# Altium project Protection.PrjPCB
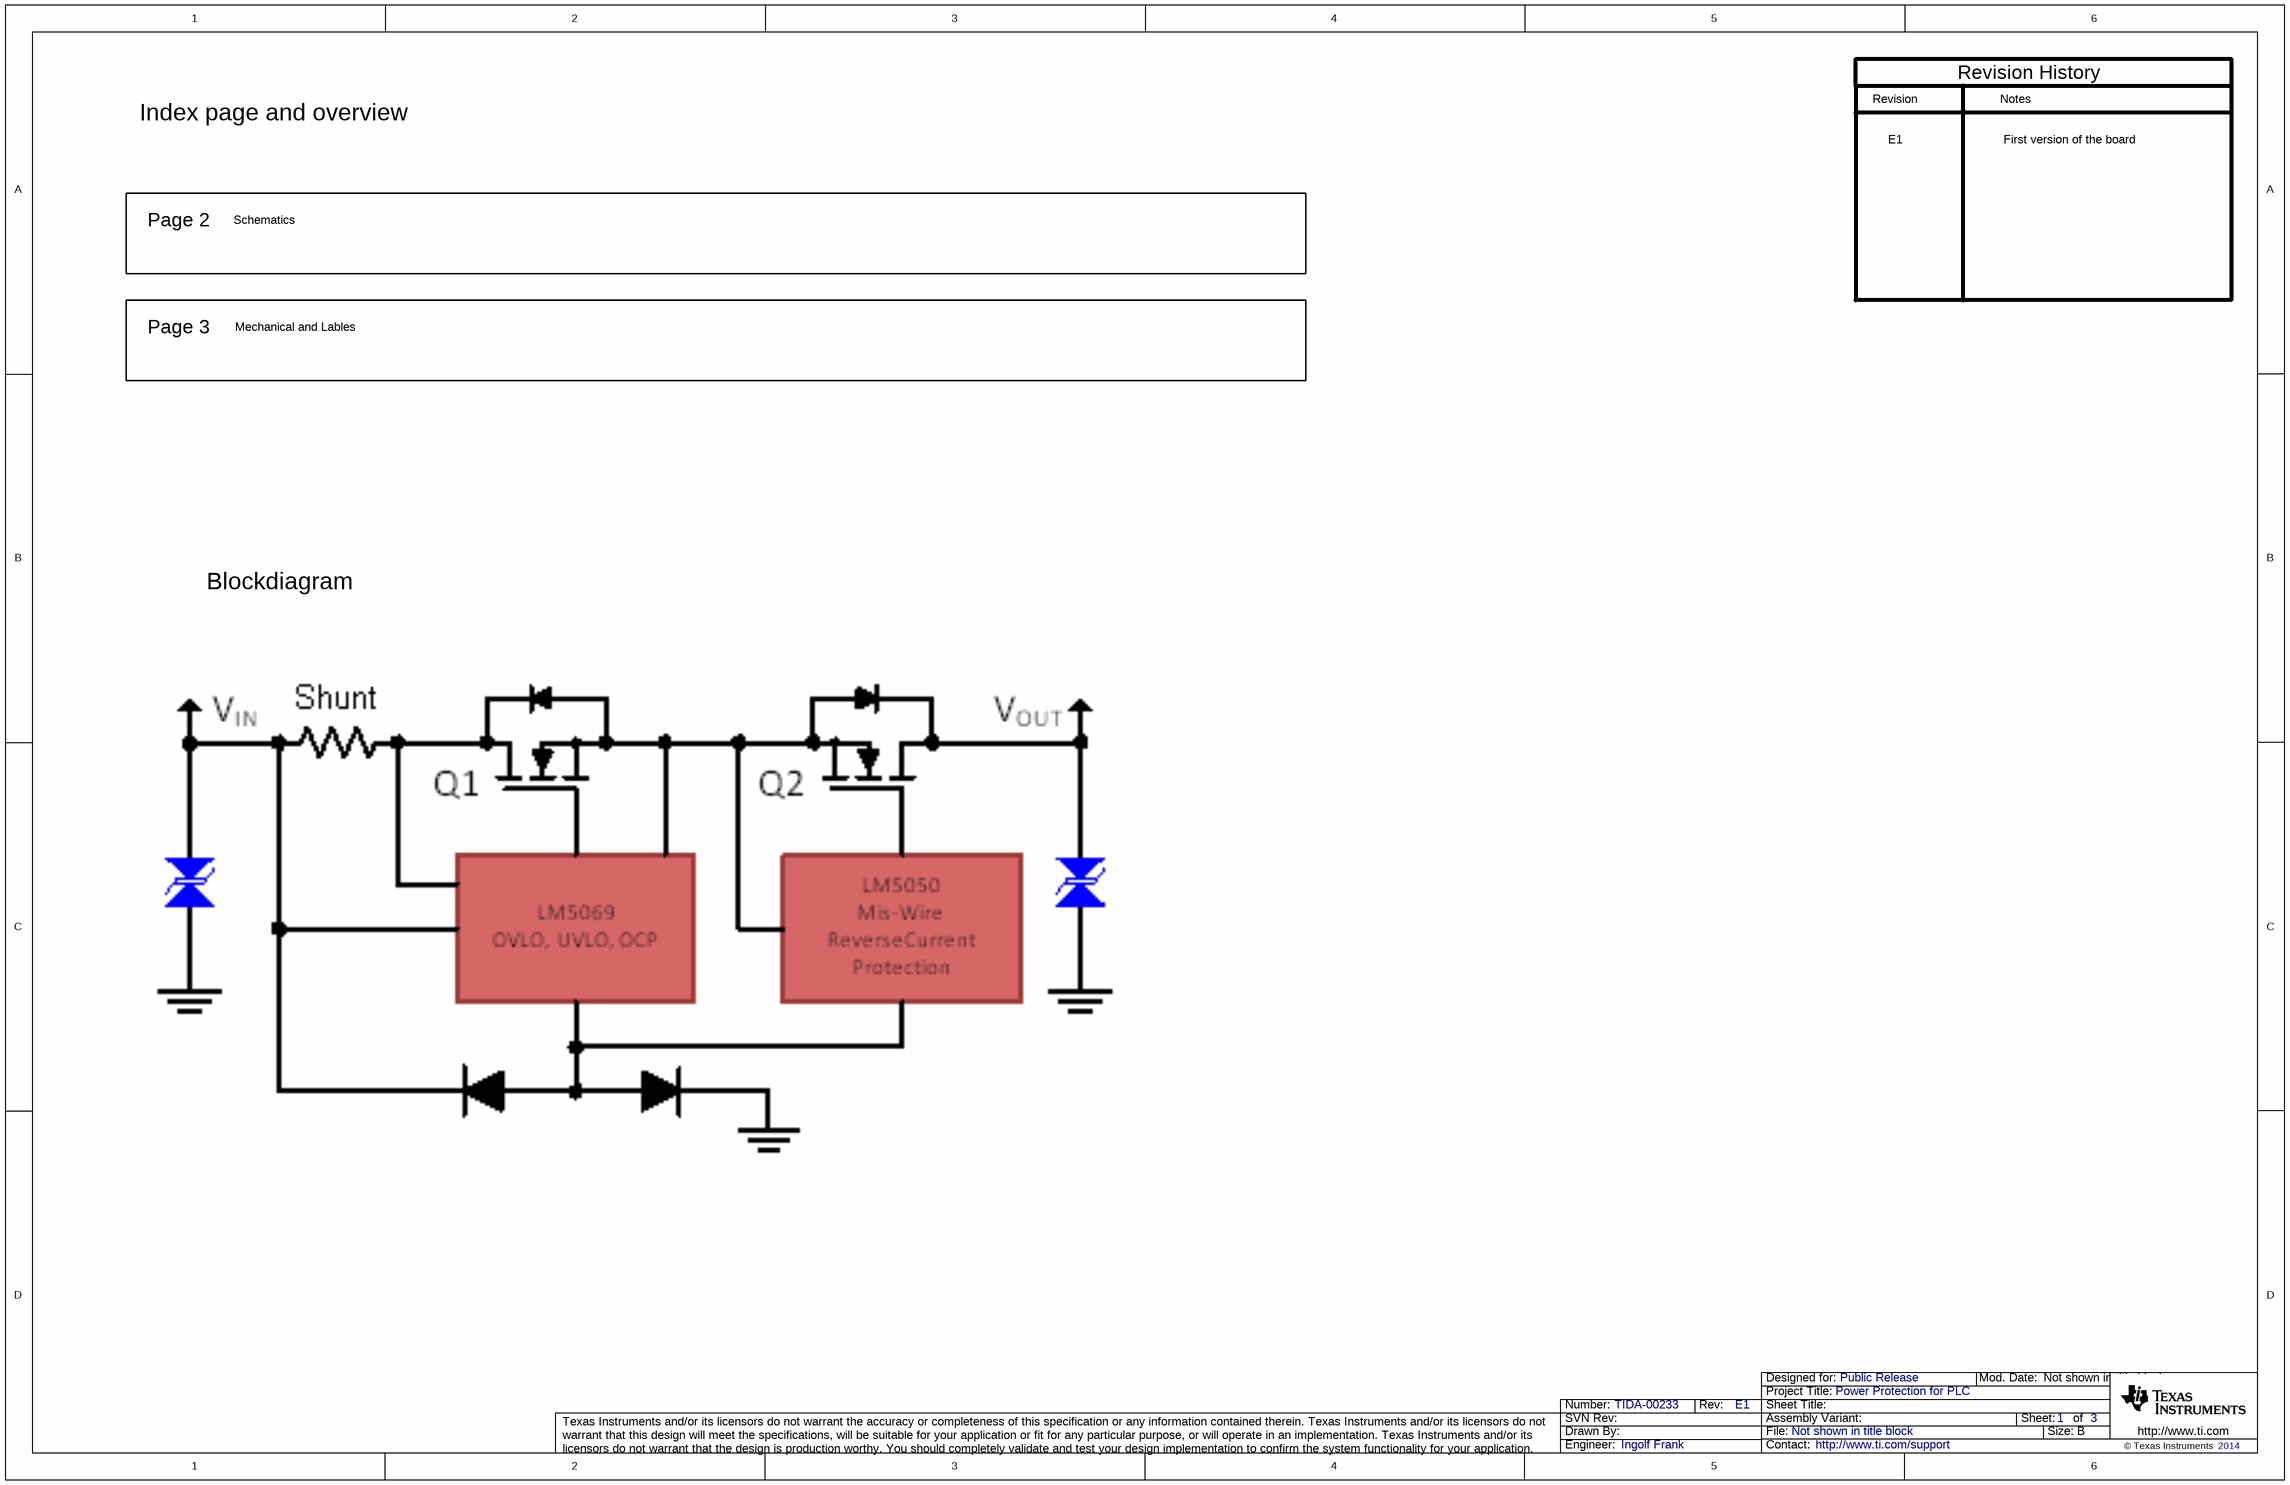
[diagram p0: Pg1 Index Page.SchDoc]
CopyrightYear: 2014; PCB_Layout: Ingolf Frank; PCB_Rev: E1; PRJ_Customer: Public Release; PRJ_Engineer: Ingolf Frank; PRJ_Number: TIDA-00233; PRJ_Title: Power Protection for PLC; SCH_Rev: E1; TechSupport: http://www.ti.com/support
3 sheets, 55 parts. Net scope: global (net labels, ports and power ports of the same name join across sheets).
Board file: Protection_var2.PcbDoc
Sheets:
  Pg1 Index Page.SchDoc
  Pg2 Protection.SchDoc
  Pg3 Hardware.SchDoc

## Sheet Pg1 Index Page.SchDoc
size 431 x 279 mm; Date: Not shown in title block; ApprovedBy: Not shown in title block; CheckedBy: Not shown in title block; Author: Not shown in title block; CompanyName: Not shown in title block; Engineer: Not shown in title block; Organization: Not shown in title block; Address1: Not shown in title block; Address2: Not shown in title block; Address3: Not shown in title block; Address4: Not shown in title block; DocumentNumber: 1; Revision: Use project parameter SCH_Rev; SheetNumber: 1; SheetTotal: 3; PageSetup: Record=PageOptions|CenterHorizontal=True|CenterVertical=True|PrintScale=1.00|XCorrection=1.00|YCorrection=1.00|PrintKind=0|BorderSize=5000000|LeftOffset=0|BottomOffset=0|Orientation=2|PaperLength=1000|PaperWidth=1000|Scale=100|PaperSource=15|PrintQuality=600|MediaType=1|DitherType=10|PaperKind=Letter|PrintScaleMode=1

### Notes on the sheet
- Revision
- Notes
- Revision History
- Index page and overview
- E1
- First version of the board
- Page 2
- Schematics
- Page 3
- Mechanical and Lables
- Blockdiagram

## Sheet Pg2 Protection.SchDoc
size 431 x 279 mm; Date: Not shown in title block; ApprovedBy: Not shown in title block; CheckedBy: Not shown in title block; Author: Not shown in title block; CompanyName: Not shown in title block; Engineer: Not shown in title block; Organization: Not shown in title block; Address1: Not shown in title block; Address2: Not shown in title block; Address3: Not shown in title block; Address4: Not shown in title block; DocumentNumber: 1; Revision: Use project parameter SCH_Rev; SheetNumber: 2; SheetTotal: 3; PageSetup: Record=PageOptions|CenterHorizontal=True|CenterVertical=True|PrintScale=0.64|XCorrection=1.00|YCorrection=1.00|PrintKind=0|BorderSize=5000000|LeftOffset=0|BottomOffset=0|Orientation=2|PaperLength=1000|PaperWidth=1000|Scale=100|PaperSource=15|PrintQuality=600|MediaType=1|DitherType=10|PaperKind=Letter|PrintScaleMode=1
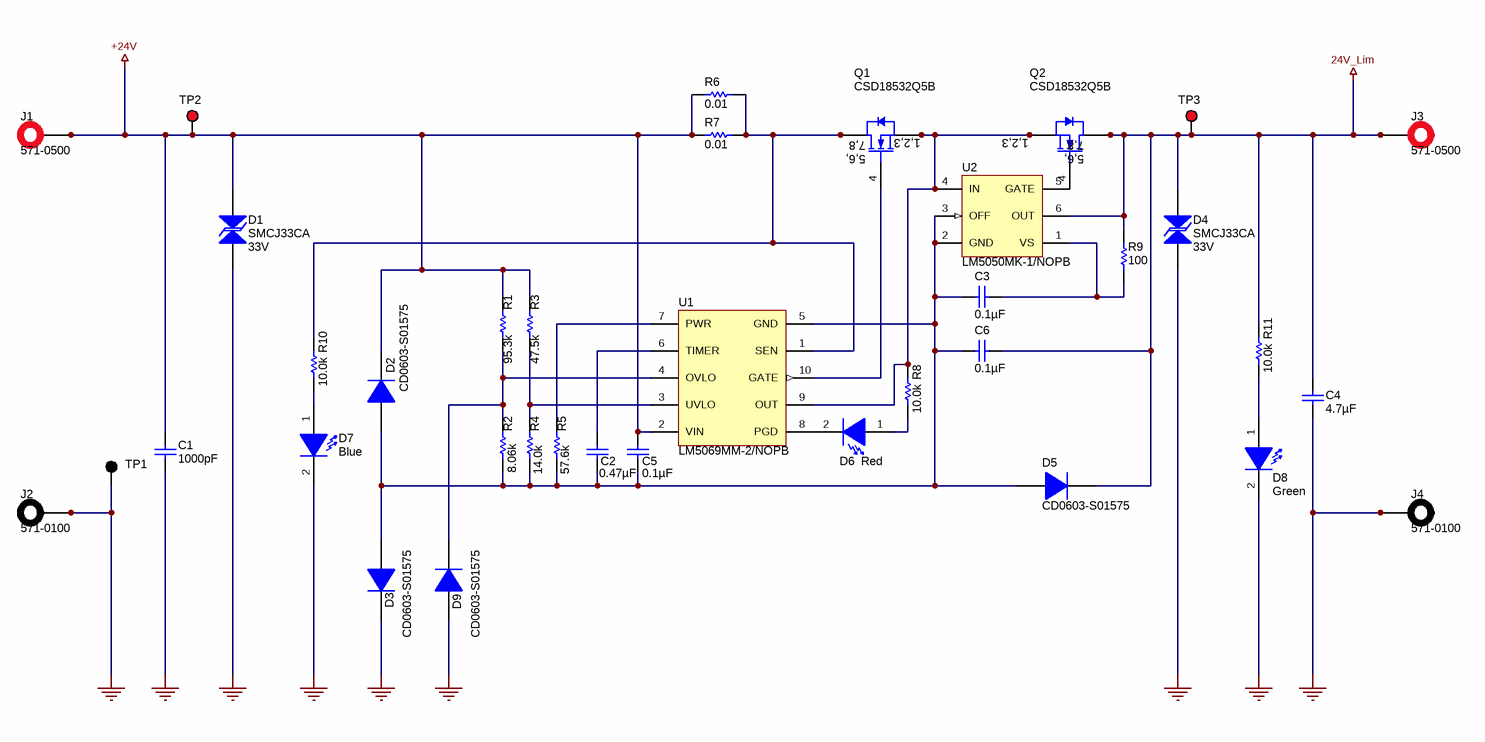
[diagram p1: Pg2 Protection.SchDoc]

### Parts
C1  ValueDisplayed: 1000pF  [0603]  (hidden comment: 06031C102JAT2A)
C2  ValueDisplayed: 0.47µF  [0603]  (hidden comment: UMK107ABJ474KA-T)
C3  ValueDisplayed: 0.1µF  [0603]  (hidden comment: GRM188R72A104KA35D)
C4  ValueDisplayed: 4.7µF  [1210M]  (hidden comment: C3225X7S2A475K200AB)
C5  ValueDisplayed: 0.1µF  [0603]  (hidden comment: GRM188R72A104KA35D)
C6  ValueDisplayed: 0.1µF  [0603]  (hidden comment: GRM188R72A104KA35D)
D1  SMCJ33CA  value 33V  [SMC]
D2  CD0603-S01575  [Diode_0603]
D3  CD0603-S01575  [Diode_0603]
D4  SMCJ33CA  value 33V  [SMC]
D5  CD0603-S01575  [Diode_0603]
D6  value Red  [LED_LTST-C190_Red]  (hidden comment: LTST-C190CKT)
D7  value Blue  [LB Q39G_BLUE]  (hidden comment: LB Q39G-L2N2-35-1)
D8  value Green  [LED_LTST-C190_G]  (hidden comment: LTST-C190KGKT)
D9  CD0603-S01575  [Diode_0603]
J1  571-0500  [571-0500]
J2  571-0100  [571-0100]
J3  571-0500  [571-0500]
J4  571-0100  [571-0100]
Q1  CSD18532Q5B  [TRANS_NexFET_Q5B]
Q2  CSD18532Q5B  [TRANS_NexFET_Q5B]
R1  value 95.3k  [0603_HV]  (hidden comment: CRCW060395K3FKEA)
R2  value 8.06k  [0603_HV]  (hidden comment: CRCW06038K06FKEA)
R3  value 47.5k  [0603_HV]  (hidden comment: CRCW060347K5FKEA)
R4  value 14.0k  [0603_HV]  (hidden comment: CRCW060314K0FKEA)
R5  value 57.6k  [0603_HV]  (hidden comment: CRCW060357K6FKEA)
R6  value 0.01  [1206]  (hidden comment: WSLP1206R0100FEA)
R7  value 0.01  [1206]  (hidden comment: WSLP1206R0100FEA)
R8  value 10.0k  [0603]  (hidden comment: CRCW060310K0FKEA)
R9  value 100  [0603]  (hidden comment: CRCW0603100RFKEA)
R10  value 10.0k  [0603]  (hidden comment: CRCW060310K0FKEA)
R11  value 10.0k  [0603]  (hidden comment: CRCW060310K0FKEA)
TP1  5001  [Keystone5001]  (value not drawn)
TP2  5000  [Keystone5000]  (value not drawn)
TP3  5000  [Keystone5000]  (value not drawn)
U1  LM5069MM-2/NOPB  [MUB10A_N]
U2  LM5050MK-1/NOPB  [DDC0006A_N]

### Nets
24V_Lim: C4.1 C6.1 D4.1 D5.1(K) J3.1 J3.2 Q2.5(D) Q2.6(D) Q2.7(D) Q2.8(D) R9.2 R11.1 TP3.1 U2.6(OUT)
+24V: C1.1 C5.1 D1.1 D2.1(K) J1.1 J1.2 R1.2 R3.2 R6.1 R7.1 TP2.1 U1.2(VIN)
GND: C1.2 C4.2 D1.2 D3.1(K) D4.2 D7.2(K) D8.2(K) D9.2(A) J2.1 J2.2 J4.1 J4.2 TP1.1
NetC2_1: C2.1 U1.6(TIMER)
NetC2_2: C2.2 C3.2 C5.2 C6.2 D2.2(A) D3.2(A) D5.2(A) R2.1 R4.1 R5.1 U1.5(GND) U2.2(GND) U2.3(OFF)
NetC3_1: C3.1 R9.1 U2.1(VS)
NetD6_1: D6.1(A) R8.2
NetD6_2: D6.2(K) U1.8(PGD)
NetD7_1: D7.1(A) R10.2
NetD8_1: D8.1(A) R11.2
NetD9_1: D9.1(K) R1.1 R2.2 U1.4(OVLO)
NetQ1_1: Q1.1(S) Q1.2(S) Q1.3(S) Q2.1(S) Q2.2(S) Q2.3(S) R8.1 U1.9(OUT) U2.4(IN)
NetQ1_4: Q1.4(G) U1.10(GATE)
NetQ1_5: Q1.5(D) Q1.6(D) Q1.7(D) Q1.8(D) R6.2 R7.2 R10.1 U1.1(SEN)
NetQ2_4: Q2.4(G) U2.5(GATE)
NetR3_1: R3.1 R4.2 U1.3(UVLO)
NetR5_2: R5.2 U1.7(PWR)

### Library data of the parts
C1 = 06031C102JAT2A: CAP, CERM, 1000pF, 100V, +/-5%, X7R, 0603; Manufacturer: AVX; Polarized: N; CompType: Capacitor; U/M: EA; Cap_F: 0.000000001; Tolerance_%: 5; ESR_Ohm: 0.276; Value1: 0.276 ohm; VDC_V: 100; TaMin_C: -55; TaMax_C: 125
C2 = UMK107ABJ474KA-T: CAP, CERM, 0.47uF, 50V, 10%, X5R, 0603; Manufacturer: Taiyo Yuden; Polarized: N; CompType: Capacitor; Cap_F: 0.00000047; Tolerance_%: 10; VDC_V: 50
C3 C5 C6 = GRM188R72A104KA35D: CAP, CERM, 0.1uF, 100V, +/-10%, X7R, 0603; Manufacturer: MuRata; Polarized: N; CompType: Capacitor; U/M: EA; Cap_F: 0.0000001; Tolerance_%: 10; Value1: Unknown; VDC_V: 100; TaMin_C: -55; TaMax_C: 125
C4 = C3225X7S2A475K200AB: CAP, CERM, 4.7uF, 100V, +/-10%, X7S, 1210; Manufacturer: TDK; Polarized: N; CompType: Capacitor; U/M: EA; Cap_F: 0.0000047; Tolerance_%: 10; Value1: Unknown; VDC_V: 100; TaMin_C: -55; TaMax_C: 125; Cap_Case: 1210
D1 D4 = SMCJ33CA: Diode, TVS, Bi, 33V, 1500W, SMC; Manufacturer: Bourns; U/M: EA; Power_W: 1500; Vr_V: 33
D2 D3 D5 D9 = CD0603-S01575: Diode, Switching, 100V, 0.15A, 0603 Diode; Manufacturer: Bourns; U/M: EA; Vf_V: 1; Value2: 1V; Io_A: 0.15; Vr_V: 100; TJmax_C: 125
D6 = LTST-C190CKT: LED, Red, SMD; Manufacturer: Lite-On; Vf_V: 2; Value2: 2V; Io_A: 0.02; Tjmax_C: 85; Power_TotalModule: 0.0625; Value1: 0.0625W; U/M: EA
D7 = LB Q39G-L2N2-35-1: LED, Blue, SMD; Manufacturer: OSRAM; Vf_V: 2.85; Value2: 2.85V; Io_A: 0.15; Tjmax_C: 95; Value1: W; U/M: EA
D8 = LTST-C190KGKT: LED, Green, SMD; Manufacturer: Lite-On; Type: AlInGaP; Vf_V: 2; Value2: 2V; Io_A: 0.03; Tjmax_C: 85; Value1: W; U/M: EA
J1 J3 = 571-0500: Standard Banana Jack, insulated, 10A, red; Manufacturer: DEM Manufacturing; CompType: Connector; SymbolCreator: codlsc; U/M: EA
J2 J4 = 571-0100: Standard Banana Jack, insulated, 10A, black; Manufacturer: DEM Manufacturing; CompType: Connector; SymbolCreator: codlsc; U/M: EA
Q1 Q2 = CSD18532Q5B: MOSFET, N-CH, 60V, 172A, SON 5x6mm; Manufacturer: Texas Instruments; Alternate Manufacturer: None; U/M: EA; ChType: N; VdsMax_V: 60; Value1: 3.3 ohm; Rdson45_Ohm: 3.3; Value2: 27 nC; QgTyp_nC: 27; Vgs_V: 1.6; IdsMax_A: 172
R1 = CRCW060395K3FKEA: RES, 95.3k ohm, 1%, 0.1W, 0603; Manufacturer: Vishay-Dale; CompType: Resistor; Res_ohm: 95300; Value_Code: 95k3; Tolerance_%: 1; Power_W: 0.1; VDC_V: 75; TempCo: 100 ppm/C; EIA_Code: E96; U/M: EA
R2 = CRCW06038K06FKEA: RES, 8.06k ohm, 1%, 0.1W, 0603; Manufacturer: Vishay-Dale; CompType: Resistor; Res_ohm: 8060; Value_Code: 8k06; Tolerance_%: 1; Power_W: 0.1; VDC_V: 75; TempCo: 100 ppm/C; EIA_Code: E96; U/M: EA
R3 = CRCW060347K5FKEA: RES, 47.5k ohm, 1%, 0.1W, 0603; Manufacturer: Vishay-Dale; CompType: Resistor; Res_ohm: 47500; Value_Code: 47k5; Tolerance_%: 1; Power_W: 0.1; VDC_V: 75; TempCo: 100 ppm/C; EIA_Code: E96; U/M: EA
R4 = CRCW060314K0FKEA: RES, 14.0k ohm, 1%, 0.1W, 0603; Manufacturer: Vishay-Dale; CompType: Resistor; Res_ohm: 14000; Value_Code: 14k0; Tolerance_%: 1; Power_W: 0.1; VDC_V: 75; TempCo: 100 ppm/C; EIA_Code: E96; U/M: EA
R5 = CRCW060357K6FKEA: RES, 57.6k ohm, 1%, 0.1W, 0603; Manufacturer: Vishay-Dale; CompType: Resistor; Res_ohm: 57600; Value_Code: 57k6; Tolerance_%: 1; Power_W: 0.1; VDC_V: 75; TempCo: 100 ppm/C; EIA_Code: E96; U/M: EA
R6 R7 = WSLP1206R0100FEA: RES, 0.01 ohm, 1%, 1W, 1206; Manufacturer: Vishay-Dale; CompType: Resistor; Value_Code: R010; Tolerance_%: 1; TempCo: 75 ppm/C; EIA_Code: E96; U/M: EA
R8 R10 R11 = CRCW060310K0FKEA: RES, 10.0k ohm, 1%, 0.1W, 0603; Manufacturer: Vishay-Dale; CompType: Resistor; Res_ohm: 10000; Value_Code: 10k0; Tolerance_%: 1; Power_W: 0.1; VDC_V: 75; TempCo: 100 ppm/C; EIA_Code: E96; U/M: EA
R9 = CRCW0603100RFKEA: RES, 100 ohm, 1%, 0.1W, 0603; Manufacturer: Vishay-Dale; CompType: Resistor; Value_Code: 100R; Tolerance_%: 1; Power_W: 0.1; VDC_V: 75; TempCo: 100 ppm/C; EIA_Code: E96; U/M: EA
TP1 = 5001: Test Point, Miniature, Black, TH; Manufacturer: Keystone; CompType: Test Point Loop; U/M: EA
TP2 TP3 = 5000: Test Point, Miniature, Red, TH; Manufacturer: Keystone; CompType: Test Point Loop; U/M: EA
U1 = LM5069MM-2/NOPB: Positive High Voltage Hot Swap / Inrush Current Controller with Power Limiting, 10-pin MSOP, Pb-Free; Manufacturer: National Semiconductor; PackageTopMarking: ZXTT*SNBB; PowerWise: N; CompType: MiscPower
U2 = LM5050MK-1/NOPB: LM5050-1 High Side OR-ing FET Controller, DDC0006A; Alternate Manufacturer: None; Manufacturer: Texas Instruments; SymbolCreator: a0411947; CompType: IC; U/M: EA

## Sheet Pg3 Hardware.SchDoc
size 431 x 279 mm; Date: Not shown in title block; ApprovedBy: Not shown in title block; CheckedBy: Not shown in title block; Author: Not shown in title block; CompanyName: Not shown in title block; Engineer: Not shown in title block; Organization: Not shown in title block; Address1: Not shown in title block; Address2: Not shown in title block; Address3: Not shown in title block; Address4: Not shown in title block; DocumentNumber: 1; Revision: Use project parameter SCH_Rev; SheetNumber: 3; SheetTotal: 3; PageSetup: Record=PageOptions|CenterHorizontal=True|CenterVertical=True|PrintScale=1.00|XCorrection=1.00|YCorrection=1.00|PrintKind=0|BorderSize=5000000|LeftOffset=0|BottomOffset=0|Orientation=2|PaperLength=1000|PaperWidth=1000|Scale=100|PaperSource=15|PrintQuality=600|MediaType=1|DitherType=10|PaperKind=Letter|PrintScaleMode=1
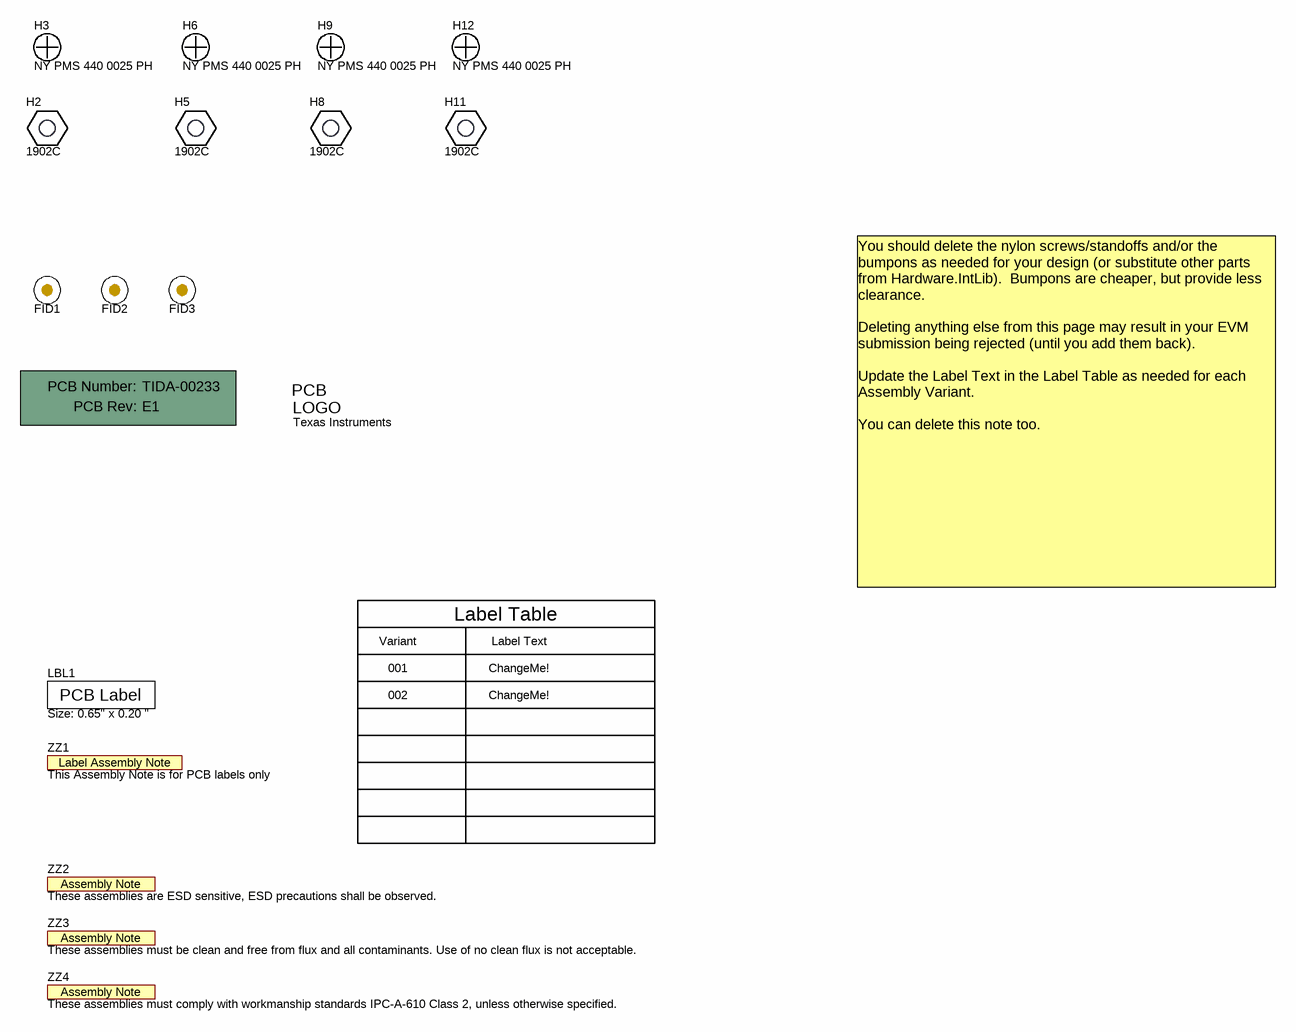
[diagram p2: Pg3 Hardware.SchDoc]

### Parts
!PCB1  Printed Circuit Board  (value not drawn)  (mechanical)
FID1  Fiducial  [Fiducial10-20]  (value not drawn)
FID2  Fiducial  [Fiducial10-20]  (value not drawn)
FID3  Fiducial  [Fiducial10-20]  (value not drawn)
H2  1902C  [Keystone_1902C]
H3  NY PMS 440 0025 PH  [NY PMS 440 0025 PH]
H5  1902C  [Keystone_1902C]
H6  NY PMS 440 0025 PH  [NY PMS 440 0025 PH]
H8  1902C  [Keystone_1902C]
H9  NY PMS 440 0025 PH  [NY PMS 440 0025 PH]
H11  1902C  [Keystone_1902C]
H12  NY PMS 440 0025 PH  [NY PMS 440 0025 PH]
LBL1  Size: 0.65" x 0.20 "  [Label_650x200]
Logo1  Texas Instruments  [TI_Stacked_SolderMask_Small]  (no BOM)
ZZ1  This Assembly Note is for PCB labels only  [AssemblyNoteLabel]  (no BOM)
ZZ2  These assemblies are ESD sensitive, ESD precautions shall be observed.  [AssemblyNote]  (no BOM)
ZZ3  These assemblies must be clean and free from flux and all contaminants. Use of no clean flux is not acceptable.  [AssemblyNote]  (no BOM)
ZZ4  These assemblies must comply with workmanship standards IPC-A-610 Class 2, unless otherwise specified.  [AssemblyNote]  (no BOM)

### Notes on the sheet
- Variant
- Label Table
- Label Text
- You should delete the nylon screws/standoffs and/or the bumpons as needed for your design (or substitute other parts from Hardware.IntLib).  Bumpons are cheaper, but provide less clearance.
  Deleting anything else from this page may result in your EVM submission being rejected (until you add them back).
  Update the Label Text in the Label Table as needed for each Assembly Variant.
  You can delete this note too.
- 001
- 002
- ChangeMe!

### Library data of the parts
!PCB1 = PCB: Manufacturer: Any; PartNumber: TIDA-00233; SymbolCreator: a0412235
FID1-FID3 = Fiducial: Fiducial mark.  There is nothing to buy or mount.; SymbolCreator: codlsc
H2 H5 H8 H11 = 1902C: Standoff, Hex, 0.5"L #4-40 Nylon; Manufacturer: Keystone; CompType: Hardware
H3 H6 H9 H12 = NY PMS 440 0025 PH: Machine Screw, Round, #4-40 x 1/4, Nylon, Philips panhead; Manufacturer: B&F Fastener Supply; CompType: Hardware; SymbolCreator: codlsc; U/M: EA
LBL1 = THT-14-423-10: Thermal Transfer Printable Labels, 0.650" W x 0.200" H - 10,000 per roll; Manufacturer: Brady; SymbolCreator: a0412235; CompType: Label
Logo1 = TI_Logo: Texas Instrument Corporate Signature; SymbolCreator: codlsc
ZZ1 = AssemblyNoteLabel: SymbolCreator: a0412235
ZZ2-ZZ4 = AssemblyNote: SymbolCreator: codlsc

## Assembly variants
001: all parts fitted
002: not fitted D5 D9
